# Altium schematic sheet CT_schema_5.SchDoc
size 368 x 245 mm
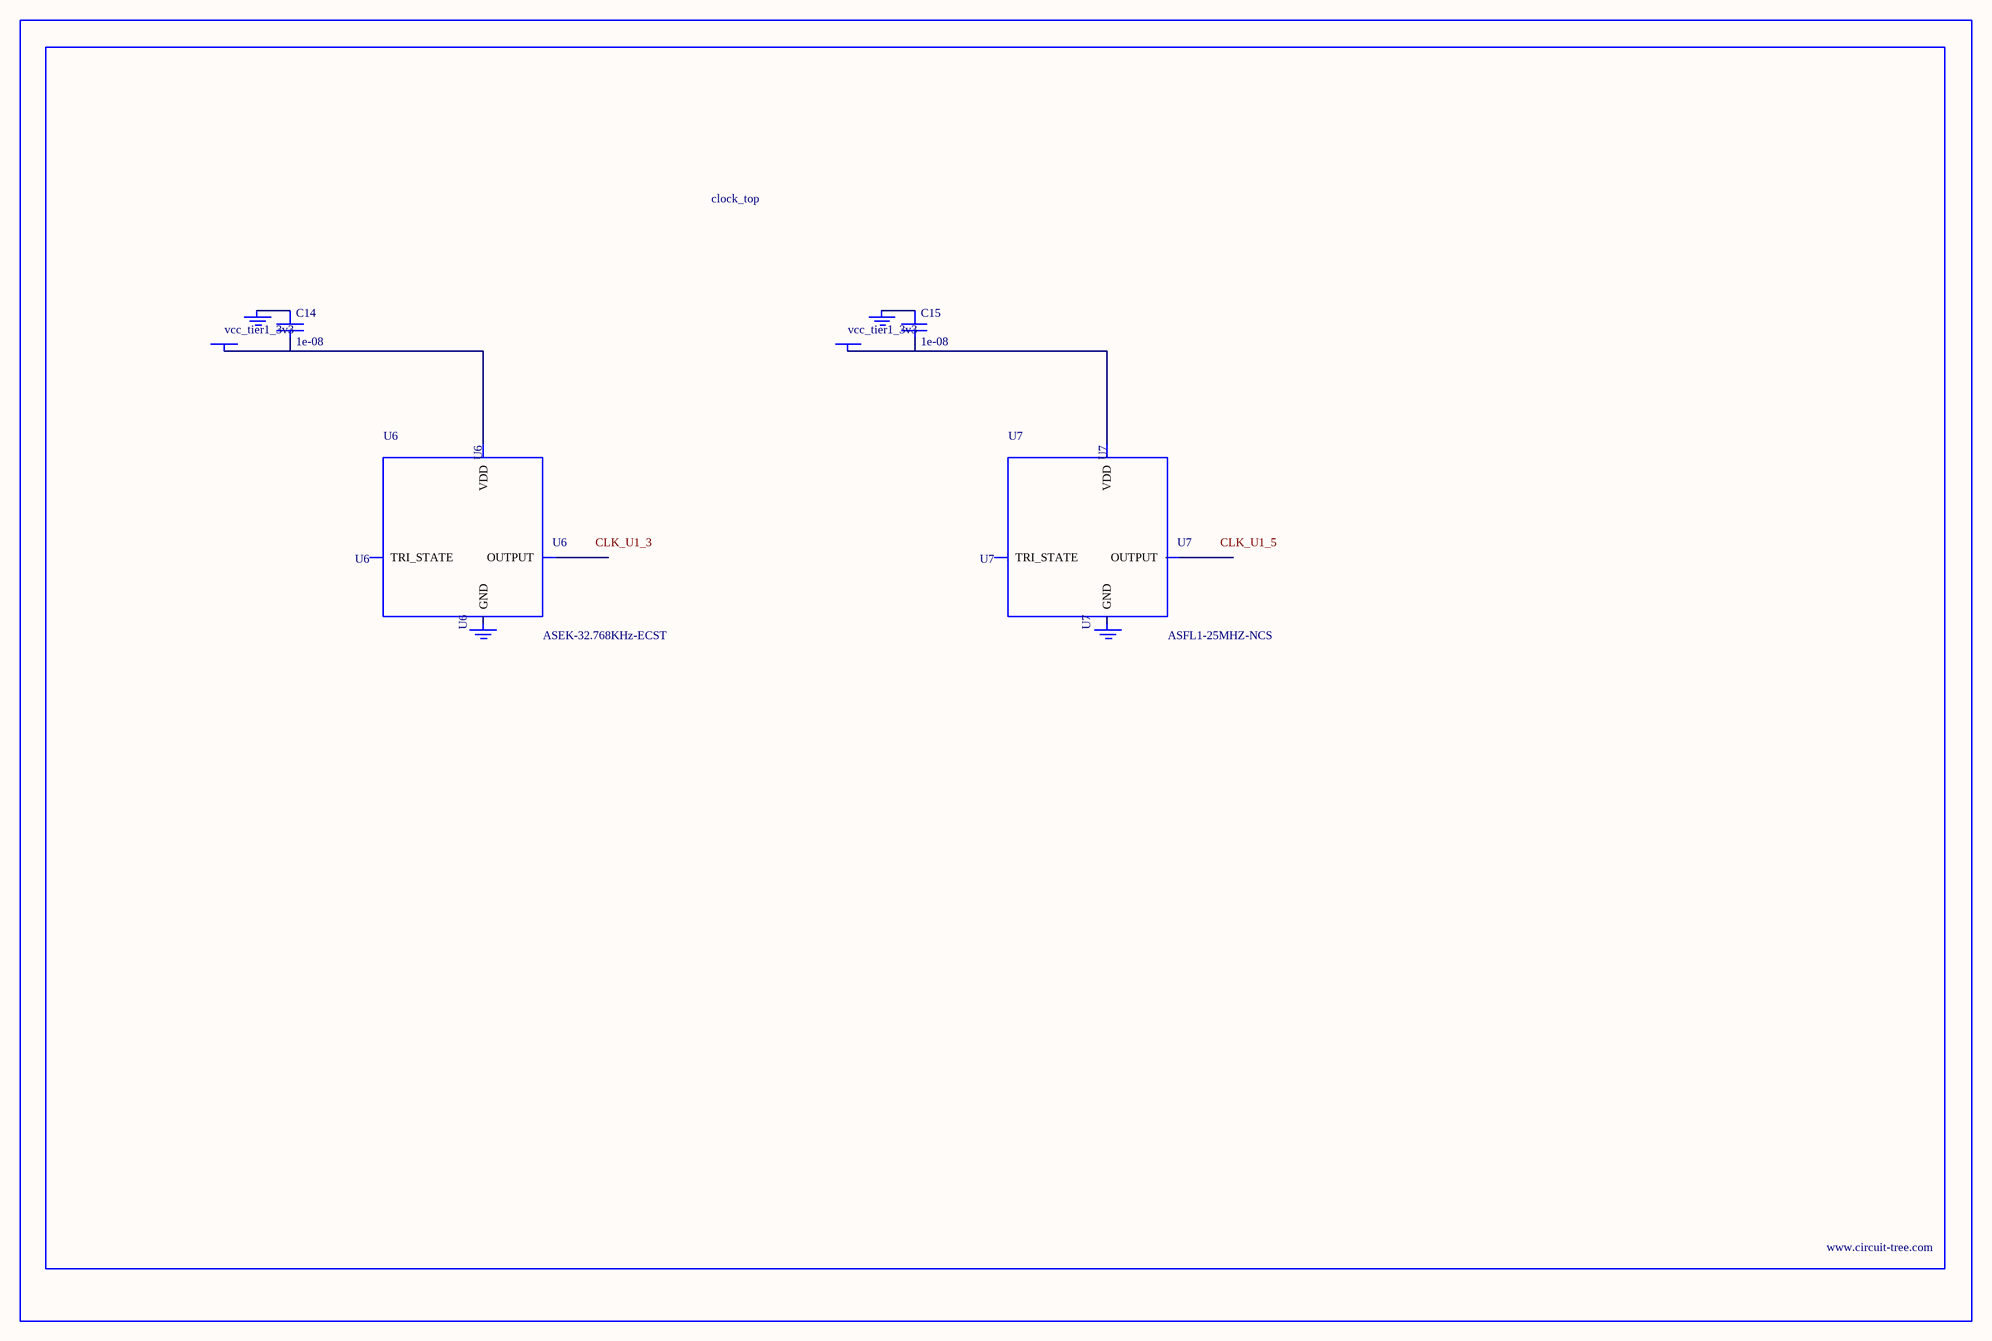
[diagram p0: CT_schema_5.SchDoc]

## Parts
BORDER4  (no value)
C14  1e-08  [C0402]
C15  1e-08  [C0402]
GND_INSTANCE_4_0  (no value)
GND_INSTANCE_4_1  (no value)
GND_INSTANCE_4_2  (no value)
GND_INSTANCE_4_3  (no value)
POWER_INSTANCE_4_0  vcc_tier1_3v3
POWER_INSTANCE_4_1  vcc_tier1_3v3
U6  ASEK-32.768KHz-ECST  [ASEK]
U7  ASFL1-25MHZ-NCS  [ASFL1]

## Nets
NetC14_1: C14.1 GND_INSTANCE_4_0.0(GND)
NetC14_2: C14.2 POWER_INSTANCE_4_0.0(PWR) U6.4(VDD)
NetC15_1: C15.1 GND_INSTANCE_4_2.0(GND)
NetC15_2: C15.2 POWER_INSTANCE_4_1.0(PWR) U7.4(VDD)

Not connected (* = marked no-connect by the designer): GND_INSTANCE_4_1 0(GND); GND_INSTANCE_4_3 0(GND); U6 1(TRI_STATE) 2(GND) 3(OUTPUT); U7 1(TRI_STATE) 2(GND) 3(OUTPUT)

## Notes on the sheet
- Labels drawn without touching a wire or pin: CLK_U1_3, CLK_U1_5

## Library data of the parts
BORDER4 = BORDER_PAGE4
C14 C15 = C0402C103K3RAC
GND_INSTANCE_4_0-GND_INSTANCE_4_3 = GND
POWER_INSTANCE_4_0 POWER_INSTANCE_4_1 = PWR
